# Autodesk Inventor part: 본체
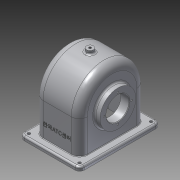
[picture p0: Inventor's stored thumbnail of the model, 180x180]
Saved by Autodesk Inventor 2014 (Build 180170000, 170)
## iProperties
Created: 2016-01
Part Number: 본체
Material: Aluminum 6061
Document SubType Name: Modeling
Designer: user
Density: 2.71 g/cm^3
Appearance: Aluminum - Flat
Mass: 847.204 g
Surface Area: 1011.63 cm^2
Volume: 312.621 cm^3
Author: user
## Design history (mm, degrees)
sketch "Sketch1"
  geometry: L1 (-52, -70)-(52, -70); L2 (52, -70)-(52, 70); L3 (52, 70)-(-52, 70); L4 (-52, 70)-(-52, -70); L5 (-52, -70)-(52, 70); L6 (52, -70)-(-52, 70); 5 further points
  constraints: 12 end point, 6 midpoint, 1 horizontal alignment, 1 vertical alignment
  dimensions: "d0" = 104 distance between parallel lines of L2 L4; "d1" = 140 distance between parallel lines of L1 L3
extrude "Extrusion1" new body sketch "Sketch1" distance "d2" = 7; taper "d3" = 0 deg
sketch "Sketch2"
  geometry: L1 (-52, -70)-(52, -70) reference; L2 (52, -70)-(52, 70) reference; L3 (52, 70)-(-52, 70) reference; L4 (-52, 70)-(-52, -70) reference; L5 (-44, 62)-(44, 62); L6 (44, 62)-(44, -62); L7 (44, -62)-(-44, -62); L8 (-44, -62)-(-44, 62); C1 r 2.5 at (-44, 62); C2 r 2.5 at (44, 62); C3 r 2.5 at (-44, -62); C4 r 2.5 at (44, -62); 1 further point
  constraints: 8 end point, 4 centre point, 4 coincident, 3 equal radius, 3 other
  dimensions: "d4" = 8 distance between parallel lines of L8 L4; "d5" = 5 diameter of C1
extrude "Extrusion2" cut sketch "Sketch2" stored distance "d6" = 7; taper "d7" = 0 deg
sketch "Sketch3"
  geometry: L1 (-38.5, -57)-(38.5, -57); L2 (38.5, -57)-(38.5, 57); L3 (38.5, 57)-(-38.5, 57); L4 (-38.5, 57)-(-38.5, -57); L5 (-38.5, -57)-(38.5, 57); L6 (38.5, -57)-(-38.5, 57); 5 further points
  constraints: 12 end point, 6 midpoint, 1 horizontal alignment, 1 vertical alignment
  dimensions: "d8" = 114 distance between parallel lines of L3 L1; "d9" = 77 distance between parallel lines of L2 L4
extrude "Extrusion3" join sketch "Sketch3" distance "d10" = 57; taper "d11" = 0 deg
sketch "Sketch4"
  geometry: L1 (0, 114)-(-57, 114) reference; L2 (-57, 0)-(-57, 114) reference; L3 (-57, 0)-(-57, 114); A1 r 57 centre (-57, 57) between (-57, 114) and (-57, 0); 1 further point
  constraints: 3 end point, 3 point on circle, 1 centre point, 1 midpoint, 1 point on line
extrude "Extrusion4" join sketch "Sketch4" distance "d12" = 77; taper "d13" = 0 deg
sketch "Sketch6"
  geometry: L1 (7, -13)-(7, 127) reference; L2 (-53, -13)-(-53, 127); L3 (7, 57)-(-53, 57); C1 r 31 at (-53, 57)
  constraints: 4 end point, 1 centre point, 1 coincident, 1 midpoint, 1 parallel
  dimensions: "d26" = 60 distance between parallel lines of L1 L2; "d27" = 62 diameter of C1
extrude "Extrusion5" join sketch "Sketch6" distance "d28" = 10; taper "d29" = 0 deg
workplane "Work Plane1"
sketch "Sketch7"
  geometry: C1 r 6 at (0, 0); 1 further point
  constraints: 1 centre point, 1 coincident
  dimensions: "d31" = 12 diameter of C1
extrude "Extrusion6" join sketch "Sketch7" stored distance "d32" = 6; taper "d33" = 0 deg
sketch "Sketch11"
  geometry: L1 (57, 7)-(-57, 7) reference; L2 (57, 7)-(57, 64) reference; L3 (-57, 7)-(-57, 64) reference; L4 (51, 64)-(51, 0); L5 (-51, 0)-(-51, 64); L6 (70, 0)-(-70, 0) reference; L7 (-70, 0)-(-70, 7) reference; L8 (70, 7)-(-70, 7) reference; L9 (70, 0)-(70, 7) reference; L10 (-51, 0)-(51, 0); C1 r 31 at (0, 60) reference; A1 r 57 centre (0, 64) between (57, 64) and (-57, 64) reference; A2 r 51 centre (0, 64) between (51, 64) and (-51, 64); 1 further point
  constraints: 6 end point, 2 point on circle, 2 point on line, 1 centre point
  dimensions: "d62" = 6 radial gap between concentric circles of A2 A1; "d63" = 102 distance between parallel lines of L4 L5; "d64" = 64 distance from line of L6 L5.end
extrude "Extrusion7" cut sketch "Sketch11" stored distance "d65" = 67; taper "d66" = 0 deg
sketch "Sketch12"
  geometry: L1 (38.5, 7)-(38.5, 64) reference; L2 (33.5, 115)-(-33.5, 115) reference; L3 (33.5, 64)-(33.5, 115) reference; L4 (-33.5, 115)-(-33.5, 64) reference; L5 (-33.5, 0)-(-33.5, 64) reference; L6 (-52, 0)-(52, 0) reference; L7 (-52, 60)-(52, 60); L8 (19.5, 60)-(19.5, 88); L9 (19.5, 88)-(33.5, 99.747); L10 (33.5, 99.747)-(33.5, 60); 1 further point
  constraints: 8 end point, 3 point on line, 1 parallel
  dimensions: "d67" = 60 distance between parallel lines of L6 L7; "d68" = 50 deg angle of L8 L9; "d70" = 56 diameter of L8.end L7
revolve "Revolution2" sketch "Sketch12" stored, may be unused: angle "d71" = 90 deg
sketch "Sketch13"
  geometry: L1 (35.5, 94.899)-(38.5, 97.416); L2 (35.5, 80)-(35.5, 94.899); L3 (19.5, 32)-(19.5, 88) reference; L4 (-33.5, 0)-(33.5, 0) reference; L5 (-33.5, 60)-(38.5, 60); L6 (38.5, 7)-(38.5, 64) reference; L7 (38.5, 60)-(38.5, 80); L8 (19.5, 88)-(33.5, 99.747) reference; L9 (35.5, 80)-(19.5, 80); L10 (38.5, 97.416)-(38.5, 80); L11 (19.5, 80)-(19.5, 60); 1 further point
  constraints: 14 end point, 4 point on line, 1 midpoint, 1 parallel
  dimensions: "d76" = 60 distance between parallel lines of L4 L5; "d77" = 40 diameter of L9 L5
revolve "Revolution3" sketch "Sketch13" stored, may be unused: angle "d78" = 90 deg
hole "Hole1" diameter "d81" = 40; stored, may be unused: countersink angle "d85" = 90 deg, drill point angle "d87" = 0 deg; dims "d79" = 10, "d80" = 10, "d82" = 6, "d83" = 4, "d84" = 2, "d86" = 8
sketch "Sketch14" dims "d88" = 48
  geometry: L1 (0, 0)-(-24, 0); C1 r 31 at (0, 0) reference; 2 further points
  constraints: 2 coincident, 2 end point, 1 horizontal alignment, 2 other
hole "Hole2" sketch "Sketch14" at (-24, 0) diameter "d89" = 2.459; stored, may be unused: countersink angle "d93" = 90 deg, drill point angle "d95" = 120 deg; dims "d90" = 6, "d91" = 4, "d92" = 2, "d94" = 8
pattern_circular "Circular Pattern1" dims angle "d97" = 360 deg
sketch "Sketch15" dims "d99" = 56
  geometry: L1 (0.71, 0)-(28, 0); C1 r 34.899 at (0, 0) reference; 3 further points
  constraints: 2 coincident, 2 end point, 1 horizontal alignment, 2 other
hole "Hole3" sketch "Sketch15" at (28, 0) diameter "d100" = 2.459; stored, may be unused: countersink angle "d104" = 90 deg, drill point angle "d106" = 120 deg; dims "d101" = 7, "d102" = 4, "d103" = 2, "d105" = 9
pattern_circular "Circular Pattern2" dims angle "d108" = 360 deg
hole "Hole4" diameter "d112" = 4.134; stored, may be unused: countersink angle "d116" = 90 deg, drill point angle "d118" = 120 deg; dims "d110" = 10, "d111" = 10, "d113" = 7, "d114" = 4, "d115" = 2, "d117" = 9
sketch "Sketch16"
  geometry: L1 (-13.5, -7)-(90.5, -7) reference; L2 (-13.5, 23)-(90.5, 23); L3 (38.5, -7)-(38.5, 37.901); 2 further points
  constraints: 4 end point, 1 coincident, 1 midpoint, 1 parallel, 1 point on line, 1 other
  dimensions: "d119" = 30 distance between parallel lines of L1 L2
emboss "Emboss1" sketch "Sketch16" dims "d0" = 104, "d1" = 140, "d120" = 0.5, "d121" = 0
fillet "Fillet1" dims "d122" = 8
fillet "Fillet2" dims "d123" = 3
fillet "Fillet3" dims "d124" = 14
fillet "Fillet4" dims "d125" = 1
chamfer "Chamfer1" distance "d126" = 1; stored, may be unused: second distance "d127" = 2, angle "d128" = 45 deg
fillet "Fillet5" dims "d129" = 3
fillet "Fillet6" dims "d130" = 3
fillet "Fillet7" dims "d131" = 3
body "Solid1"
node "Projected Loop1"
node "Projected Loop2"
other parameters: "d30" = 127, "d51" = 50 deg, "d56" = 50 deg
